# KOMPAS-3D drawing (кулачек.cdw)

Views: Слева 4, Слева, Проекционный вид 5
Referenced files in C:\Users\Игорь\Desktop\авто\1\: 17.m3d
Referenced files: кулачек.cdw
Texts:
  Кулачек
  Игорь
  Силумин АК12ж ГОСТ 1583-93
Dimensions and other numbers on the sheet: 2; 4; 6,5; 5; 6; 3; 5:1; 1; 0; 7; 8; 9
